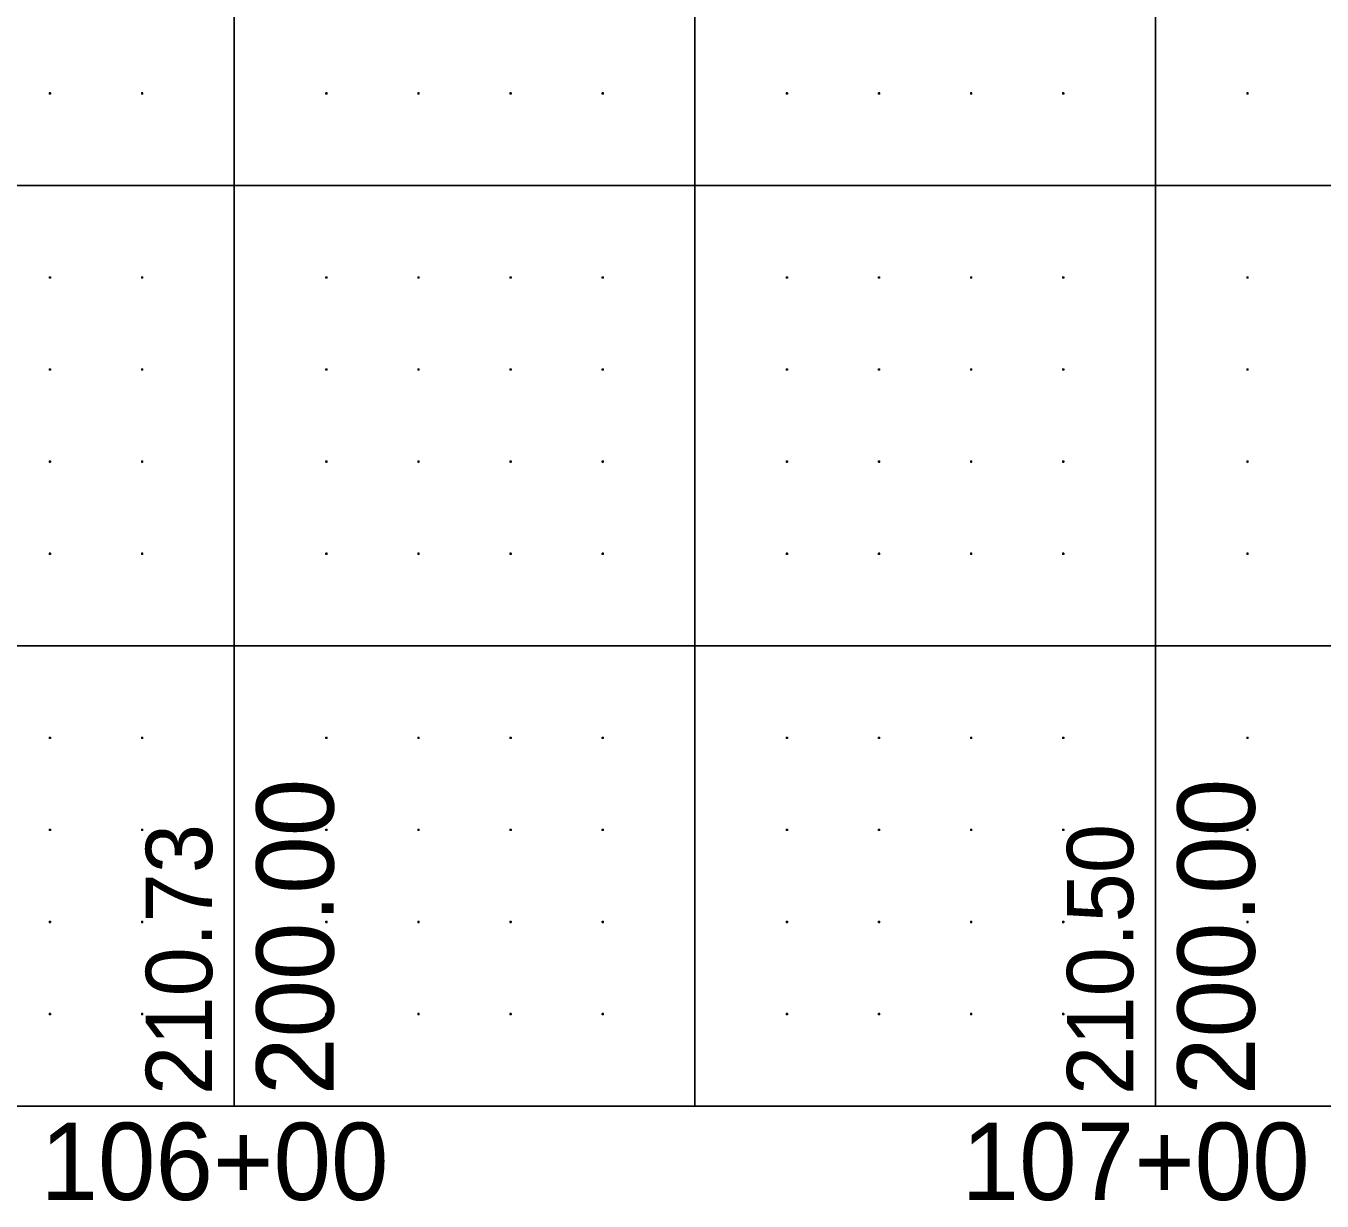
# Model space of a CAD drawing. Extents: x 471 to 2121, y 140 to 650.
# Drawn here: x 1213.4 to 1354.2, y 139.7 to 267.3 of the extents above; entities that cross this region are included whole.
import ezdxf

# ---------------------------------------------------------------- set-up
doc = ezdxf.new("R2010")
doc.units = 0
for name, color, linetype in [('DSN_DRFT_Border Grid', 7, 'Continuous'), ('DSN_RDWY_Prof Annotation', 7, 'Continuous'), ('EX_Profile Annotation', 7, 'Continuous')]:
    doc.layers.add(name, color=color, linetype=linetype)

msp = doc.modelspace()

# ---------------------------------------------------------------- linework, layer by layer
at = {"layer": 'DSN_DRFT_Border Grid'}
for p, q in [((1236.06, 150), (1236.06, 650)), ((1236.06, 150), (1236.06, 650)), ((1286.06, 150), (1286.06, 650)), ((1286.06, 150), (1286.06, 650)), ((1336.06, 150), (1336.06, 650)), ((1336.06, 150), (1336.06, 650)), ((1216.18, 260), (1215.94, 260)), ((1216.18, 260), (1215.94, 260)), ((1216.06, 260.12), (1216.06, 259.88)), ((1216.06, 260.12), (1216.06, 259.88)), ((1226.18, 260), (1225.94, 260)), ((1226.18, 260), (1225.94, 260)), ((1226.06, 260.12), (1226.06, 259.88)), ((1226.06, 260.12), (1226.06, 259.88)), ((1246.18, 260), (1245.94, 260)), ((1246.18, 260), (1245.94, 260)), ((1246.06, 260.12), (1246.06, 259.88)), ((1246.06, 260.12), (1246.06, 259.88)), ((1256.18, 260), (1255.94, 260)), ((1256.18, 260), (1255.94, 260)), ((1256.06, 260.12), (1256.06, 259.88)), ((1256.06, 260.12), (1256.06, 259.88)), ((1266.18, 260), (1265.94, 260)), ((1266.18, 260), (1265.94, 260)), ((1266.06, 260.12), (1266.06, 259.88)), ((1266.06, 260.12), (1266.06, 259.88)), ((1276.18, 260), (1275.94, 260)), ((1276.18, 260), (1275.94, 260)), ((1276.06, 260.12), (1276.06, 259.88)), ((1276.06, 260.12), (1276.06, 259.88)), ((1296.18, 260), (1295.94, 260)), ((1296.18, 260), (1295.94, 260)), ((1296.06, 260.12), (1296.06, 259.88)), ((1296.06, 260.12), (1296.06, 259.88)), ((1306.18, 260), (1305.94, 260)), ((1306.18, 260), (1305.94, 260)), ((1306.06, 260.12), (1306.06, 259.88)), ((1306.06, 260.12), (1306.06, 259.88)), ((1316.18, 260), (1315.94, 260)), ((1316.18, 260), (1315.94, 260)), ((1316.06, 260.12), (1316.06, 259.88)), ((1316.06, 260.12), (1316.06, 259.88)), ((1326.18, 260), (1325.94, 260)), ((1326.18, 260), (1325.94, 260)), ((1326.06, 260.12), (1326.06, 259.88)), ((1326.06, 260.12), (1326.06, 259.88)), ((1346.18, 260), (1345.94, 260)), ((1346.18, 260), (1345.94, 260)), ((1346.06, 260.12), (1346.06, 259.88)), ((1346.06, 260.12), (1346.06, 259.88)), ((521.06, 250), (2071.06, 250)), ((521.06, 250), (2071.06, 250)), ((1216.18, 240), (1215.94, 240)), ((1216.18, 240), (1215.94, 240)), ((1216.06, 240.12), (1216.06, 239.88)), ((1216.06, 240.12), (1216.06, 239.88)), ((1226.18, 240), (1225.94, 240)), ((1226.18, 240), (1225.94, 240)), ((1226.06, 240.12), (1226.06, 239.88)), ((1226.06, 240.12), (1226.06, 239.88)), ((1246.18, 240), (1245.94, 240)), ((1246.18, 240), (1245.94, 240)), ((1246.06, 240.12), (1246.06, 239.88)), ((1246.06, 240.12), (1246.06, 239.88)), ((1256.18, 240), (1255.94, 240)), ((1256.18, 240), (1255.94, 240)), ((1256.06, 240.12), (1256.06, 239.88)), ((1256.06, 240.12), (1256.06, 239.88)), ((1266.18, 240), (1265.94, 240)), ((1266.18, 240), (1265.94, 240)), ((1266.06, 240.12), (1266.06, 239.88)), ((1266.06, 240.12), (1266.06, 239.88)), ((1276.18, 240), (1275.94, 240)), ((1276.18, 240), (1275.94, 240)), ((1276.06, 240.12), (1276.06, 239.88)), ((1276.06, 240.12), (1276.06, 239.88)), ((1296.18, 240), (1295.94, 240)), ((1296.18, 240), (1295.94, 240)), ((1296.06, 240.12), (1296.06, 239.88)), ((1296.06, 240.12), (1296.06, 239.88)), ((1306.18, 240), (1305.94, 240)), ((1306.18, 240), (1305.94, 240)), ((1306.06, 240.12), (1306.06, 239.88)), ((1306.06, 240.12), (1306.06, 239.88)), ((1316.18, 240), (1315.94, 240)), ((1316.18, 240), (1315.94, 240)), ((1316.06, 240.12), (1316.06, 239.88)), ((1316.06, 240.12), (1316.06, 239.88)), ((1326.18, 240), (1325.94, 240)), ((1326.18, 240), (1325.94, 240)), ((1326.06, 240.12), (1326.06, 239.88)), ((1326.06, 240.12), (1326.06, 239.88)), ((1346.18, 240), (1345.94, 240)), ((1346.18, 240), (1345.94, 240)), ((1346.06, 240.12), (1346.06, 239.88)), ((1346.06, 240.12), (1346.06, 239.88)), ((1216.18, 230), (1215.94, 230)), ((1216.18, 230), (1215.94, 230)), ((1216.06, 230.12), (1216.06, 229.88)), ((1216.06, 230.12), (1216.06, 229.88)), ((1226.18, 230), (1225.94, 230)), ((1226.18, 230), (1225.94, 230)), ((1226.06, 230.12), (1226.06, 229.88)), ((1226.06, 230.12), (1226.06, 229.88)), ((1246.18, 230), (1245.94, 230)), ((1246.18, 230), (1245.94, 230)), ((1246.06, 230.12), (1246.06, 229.88)), ((1246.06, 230.12), (1246.06, 229.88)), ((1256.18, 230), (1255.94, 230)), ((1256.18, 230), (1255.94, 230)), ((1256.06, 230.12), (1256.06, 229.88)), ((1256.06, 230.12), (1256.06, 229.88)), ((1266.18, 230), (1265.94, 230)), ((1266.18, 230), (1265.94, 230)), ((1266.06, 230.12), (1266.06, 229.88)), ((1266.06, 230.12), (1266.06, 229.88)), ((1276.18, 230), (1275.94, 230)), ((1276.18, 230), (1275.94, 230)), ((1276.06, 230.12), (1276.06, 229.88)), ((1276.06, 230.12), (1276.06, 229.88)), ((1296.18, 230), (1295.94, 230)), ((1296.18, 230), (1295.94, 230)), ((1296.06, 230.12), (1296.06, 229.88)), ((1296.06, 230.12), (1296.06, 229.88)), ((1306.18, 230), (1305.94, 230)), ((1306.18, 230), (1305.94, 230)), ((1306.06, 230.12), (1306.06, 229.88)), ((1306.06, 230.12), (1306.06, 229.88)), ((1316.18, 230), (1315.94, 230)), ((1316.18, 230), (1315.94, 230)), ((1316.06, 230.12), (1316.06, 229.88)), ((1316.06, 230.12), (1316.06, 229.88)), ((1326.18, 230), (1325.94, 230)), ((1326.18, 230), (1325.94, 230)), ((1326.06, 230.12), (1326.06, 229.88)), ((1326.06, 230.12), (1326.06, 229.88)), ((1346.18, 230), (1345.94, 230)), ((1346.18, 230), (1345.94, 230)), ((1346.06, 230.12), (1346.06, 229.88)), ((1346.06, 230.12), (1346.06, 229.88)), ((1216.18, 220), (1215.94, 220)), ((1216.18, 220), (1215.94, 220)), ((1216.06, 220.12), (1216.06, 219.88)), ((1216.06, 220.12), (1216.06, 219.88)), ((1226.18, 220), (1225.94, 220)), ((1226.18, 220), (1225.94, 220)), ((1226.06, 220.12), (1226.06, 219.88)), ((1226.06, 220.12), (1226.06, 219.88)), ((1246.18, 220), (1245.94, 220)), ((1246.18, 220), (1245.94, 220)), ((1246.06, 220.12), (1246.06, 219.88)), ((1246.06, 220.12), (1246.06, 219.88)), ((1256.18, 220), (1255.94, 220)), ((1256.18, 220), (1255.94, 220)), ((1256.06, 220.12), (1256.06, 219.88)), ((1256.06, 220.12), (1256.06, 219.88)), ((1266.18, 220), (1265.94, 220)), ((1266.18, 220), (1265.94, 220)), ((1266.06, 220.12), (1266.06, 219.88)), ((1266.06, 220.12), (1266.06, 219.88)), ((1276.18, 220), (1275.94, 220)), ((1276.18, 220), (1275.94, 220)), ((1276.06, 220.12), (1276.06, 219.88)), ((1276.06, 220.12), (1276.06, 219.88)), ((1296.18, 220), (1295.94, 220)), ((1296.18, 220), (1295.94, 220)), ((1296.06, 220.12), (1296.06, 219.88)), ((1296.06, 220.12), (1296.06, 219.88)), ((1306.18, 220), (1305.94, 220)), ((1306.18, 220), (1305.94, 220)), ((1306.06, 220.12), (1306.06, 219.88)), ((1306.06, 220.12), (1306.06, 219.88)), ((1316.18, 220), (1315.94, 220)), ((1316.18, 220), (1315.94, 220)), ((1316.06, 220.12), (1316.06, 219.88)), ((1316.06, 220.12), (1316.06, 219.88)), ((1326.18, 220), (1325.94, 220)), ((1326.18, 220), (1325.94, 220)), ((1326.06, 220.12), (1326.06, 219.88)), ((1326.06, 220.12), (1326.06, 219.88)), ((1346.18, 220), (1345.94, 220)), ((1346.18, 220), (1345.94, 220)), ((1346.06, 220.12), (1346.06, 219.88)), ((1346.06, 220.12), (1346.06, 219.88)), ((1216.18, 210), (1215.94, 210)), ((1216.18, 210), (1215.94, 210)), ((1216.06, 210.12), (1216.06, 209.88)), ((1216.06, 210.12), (1216.06, 209.88)), ((1226.18, 210), (1225.94, 210)), ((1226.18, 210), (1225.94, 210)), ((1226.06, 210.12), (1226.06, 209.88)), ((1226.06, 210.12), (1226.06, 209.88)), ((1246.18, 210), (1245.94, 210)), ((1246.18, 210), (1245.94, 210)), ((1246.06, 210.12), (1246.06, 209.88)), ((1246.06, 210.12), (1246.06, 209.88)), ((1256.18, 210), (1255.94, 210)), ((1256.18, 210), (1255.94, 210)), ((1256.06, 210.12), (1256.06, 209.88)), ((1256.06, 210.12), (1256.06, 209.88)), ((1266.18, 210), (1265.94, 210)), ((1266.18, 210), (1265.94, 210)), ((1266.06, 210.12), (1266.06, 209.88)), ((1266.06, 210.12), (1266.06, 209.88)), ((1276.18, 210), (1275.94, 210)), ((1276.18, 210), (1275.94, 210)), ((1276.06, 210.12), (1276.06, 209.88)), ((1276.06, 210.12), (1276.06, 209.88)), ((1296.18, 210), (1295.94, 210)), ((1296.18, 210), (1295.94, 210)), ((1296.06, 210.12), (1296.06, 209.88)), ((1296.06, 210.12), (1296.06, 209.88)), ((1306.18, 210), (1305.94, 210)), ((1306.18, 210), (1305.94, 210)), ((1306.06, 210.12), (1306.06, 209.88)), ((1306.06, 210.12), (1306.06, 209.88)), ((1316.18, 210), (1315.94, 210)), ((1316.18, 210), (1315.94, 210)), ((1316.06, 210.12), (1316.06, 209.88)), ((1316.06, 210.12), (1316.06, 209.88)), ((1326.18, 210), (1325.94, 210)), ((1326.18, 210), (1325.94, 210)), ((1326.06, 210.12), (1326.06, 209.88)), ((1326.06, 210.12), (1326.06, 209.88)), ((1346.18, 210), (1345.94, 210)), ((1346.18, 210), (1345.94, 210)), ((1346.06, 210.12), (1346.06, 209.88)), ((1346.06, 210.12), (1346.06, 209.88)), ((521.06, 200), (2071.06, 200)), ((521.06, 200), (2071.06, 200)), ((1216.18, 190), (1215.94, 190)), ((1216.18, 190), (1215.94, 190)), ((1216.06, 190.12), (1216.06, 189.88)), ((1216.06, 190.12), (1216.06, 189.88)), ((1226.18, 190), (1225.94, 190)), ((1226.18, 190), (1225.94, 190)), ((1226.06, 190.12), (1226.06, 189.88)), ((1226.06, 190.12), (1226.06, 189.88)), ((1246.18, 190), (1245.94, 190)), ((1246.18, 190), (1245.94, 190)), ((1246.06, 190.12), (1246.06, 189.88)), ((1246.06, 190.12), (1246.06, 189.88)), ((1256.18, 190), (1255.94, 190)), ((1256.18, 190), (1255.94, 190)), ((1256.06, 190.12), (1256.06, 189.88)), ((1256.06, 190.12), (1256.06, 189.88)), ((1266.18, 190), (1265.94, 190)), ((1266.18, 190), (1265.94, 190)), ((1266.06, 190.12), (1266.06, 189.88)), ((1266.06, 190.12), (1266.06, 189.88)), ((1276.18, 190), (1275.94, 190)), ((1276.18, 190), (1275.94, 190)), ((1276.06, 190.12), (1276.06, 189.88)), ((1276.06, 190.12), (1276.06, 189.88)), ((1296.18, 190), (1295.94, 190)), ((1296.18, 190), (1295.94, 190)), ((1296.06, 190.12), (1296.06, 189.88)), ((1296.06, 190.12), (1296.06, 189.88)), ((1306.18, 190), (1305.94, 190)), ((1306.18, 190), (1305.94, 190)), ((1306.06, 190.12), (1306.06, 189.88)), ((1306.06, 190.12), (1306.06, 189.88)), ((1316.18, 190), (1315.94, 190)), ((1316.18, 190), (1315.94, 190)), ((1316.06, 190.12), (1316.06, 189.88)), ((1316.06, 190.12), (1316.06, 189.88)), ((1326.18, 190), (1325.94, 190)), ((1326.18, 190), (1325.94, 190)), ((1326.06, 190.12), (1326.06, 189.88)), ((1326.06, 190.12), (1326.06, 189.88)), ((1346.18, 190), (1345.94, 190)), ((1346.18, 190), (1345.94, 190)), ((1346.06, 190.12), (1346.06, 189.88)), ((1346.06, 190.12), (1346.06, 189.88)), ((1216.06, 180.12), (1216.06, 179.88)), ((1216.06, 180.12), (1216.06, 179.88)), ((1226.06, 180.12), (1226.06, 179.88)), ((1226.06, 180.12), (1226.06, 179.88)), ((1246.06, 180.12), (1246.06, 179.88)), ((1246.06, 180.12), (1246.06, 179.88)), ((1256.06, 180.12), (1256.06, 179.88)), ((1256.06, 180.12), (1256.06, 179.88)), ((1266.06, 180.12), (1266.06, 179.88)), ((1266.06, 180.12), (1266.06, 179.88)), ((1276.06, 180.12), (1276.06, 179.88)), ((1276.06, 180.12), (1276.06, 179.88)), ((1296.06, 180.12), (1296.06, 179.88)), ((1296.06, 180.12), (1296.06, 179.88)), ((1306.06, 180.12), (1306.06, 179.88)), ((1306.06, 180.12), (1306.06, 179.88)), ((1316.06, 180.12), (1316.06, 179.88)), ((1316.06, 180.12), (1316.06, 179.88)), ((1326.06, 180.12), (1326.06, 179.88)), ((1326.06, 180.12), (1326.06, 179.88)), ((1346.06, 180.12), (1346.06, 179.88)), ((1346.06, 180.12), (1346.06, 179.88)), ((1216.18, 180), (1215.94, 180)), ((1216.18, 180), (1215.94, 180)), ((1226.18, 180), (1225.94, 180)), ((1226.18, 180), (1225.94, 180)), ((1246.18, 180), (1245.94, 180)), ((1246.18, 180), (1245.94, 180)), ((1256.18, 180), (1255.94, 180)), ((1256.18, 180), (1255.94, 180)), ((1266.18, 180), (1265.94, 180)), ((1266.18, 180), (1265.94, 180)), ((1276.18, 180), (1275.94, 180)), ((1276.18, 180), (1275.94, 180)), ((1296.18, 180), (1295.94, 180)), ((1296.18, 180), (1295.94, 180)), ((1306.18, 180), (1305.94, 180)), ((1306.18, 180), (1305.94, 180)), ((1316.18, 180), (1315.94, 180)), ((1316.18, 180), (1315.94, 180)), ((1326.18, 180), (1325.94, 180)), ((1326.18, 180), (1325.94, 180)), ((1346.18, 180), (1345.94, 180)), ((1346.18, 180), (1345.94, 180)), ((1216.18, 170), (1215.94, 170)), ((1216.18, 170), (1215.94, 170)), ((1216.06, 170.12), (1216.06, 169.88)), ((1216.06, 170.12), (1216.06, 169.88)), ((1226.18, 170), (1225.94, 170)), ((1226.18, 170), (1225.94, 170)), ((1226.06, 170.12), (1226.06, 169.88)), ((1226.06, 170.12), (1226.06, 169.88)), ((1246.18, 170), (1245.94, 170)), ((1246.18, 170), (1245.94, 170)), ((1246.06, 170.12), (1246.06, 169.88)), ((1246.06, 170.12), (1246.06, 169.88)), ((1256.18, 170), (1255.94, 170)), ((1256.18, 170), (1255.94, 170)), ((1256.06, 170.12), (1256.06, 169.88)), ((1256.06, 170.12), (1256.06, 169.88)), ((1266.18, 170), (1265.94, 170)), ((1266.18, 170), (1265.94, 170)), ((1266.06, 170.12), (1266.06, 169.88)), ((1266.06, 170.12), (1266.06, 169.88)), ((1276.18, 170), (1275.94, 170)), ((1276.18, 170), (1275.94, 170)), ((1276.06, 170.12), (1276.06, 169.88)), ((1276.06, 170.12), (1276.06, 169.88)), ((1296.18, 170), (1295.94, 170)), ((1296.18, 170), (1295.94, 170)), ((1296.06, 170.12), (1296.06, 169.88)), ((1296.06, 170.12), (1296.06, 169.88)), ((1306.18, 170), (1305.94, 170)), ((1306.18, 170), (1305.94, 170)), ((1306.06, 170.12), (1306.06, 169.88)), ((1306.06, 170.12), (1306.06, 169.88)), ((1316.18, 170), (1315.94, 170)), ((1316.18, 170), (1315.94, 170)), ((1316.06, 170.12), (1316.06, 169.88)), ((1316.06, 170.12), (1316.06, 169.88)), ((1326.18, 170), (1325.94, 170)), ((1326.18, 170), (1325.94, 170)), ((1326.06, 170.12), (1326.06, 169.88)), ((1326.06, 170.12), (1326.06, 169.88)), ((1346.18, 170), (1345.94, 170)), ((1346.18, 170), (1345.94, 170)), ((1346.06, 170.12), (1346.06, 169.88)), ((1346.06, 170.12), (1346.06, 169.88)), ((1216.18, 160), (1215.94, 160)), ((1216.18, 160), (1215.94, 160)), ((1216.06, 160.12), (1216.06, 159.88)), ((1216.06, 160.12), (1216.06, 159.88)), ((1226.18, 160), (1225.94, 160)), ((1226.18, 160), (1225.94, 160)), ((1226.06, 160.12), (1226.06, 159.88)), ((1226.06, 160.12), (1226.06, 159.88)), ((1246.18, 160), (1245.94, 160)), ((1246.18, 160), (1245.94, 160)), ((1246.06, 160.12), (1246.06, 159.88)), ((1246.06, 160.12), (1246.06, 159.88)), ((1256.18, 160), (1255.94, 160)), ((1256.18, 160), (1255.94, 160)), ((1256.06, 160.12), (1256.06, 159.88)), ((1256.06, 160.12), (1256.06, 159.88)), ((1266.18, 160), (1265.94, 160)), ((1266.18, 160), (1265.94, 160)), ((1266.06, 160.12), (1266.06, 159.88)), ((1266.06, 160.12), (1266.06, 159.88)), ((1276.18, 160), (1275.94, 160)), ((1276.18, 160), (1275.94, 160)), ((1276.06, 160.12), (1276.06, 159.88)), ((1276.06, 160.12), (1276.06, 159.88)), ((1296.18, 160), (1295.94, 160)), ((1296.18, 160), (1295.94, 160)), ((1296.06, 160.12), (1296.06, 159.88)), ((1296.06, 160.12), (1296.06, 159.88)), ((1306.18, 160), (1305.94, 160)), ((1306.18, 160), (1305.94, 160)), ((1306.06, 160.12), (1306.06, 159.88)), ((1306.06, 160.12), (1306.06, 159.88)), ((1316.18, 160), (1315.94, 160)), ((1316.18, 160), (1315.94, 160)), ((1316.06, 160.12), (1316.06, 159.88)), ((1316.06, 160.12), (1316.06, 159.88)), ((1326.18, 160), (1325.94, 160)), ((1326.18, 160), (1325.94, 160)), ((1326.06, 160.12), (1326.06, 159.88)), ((1326.06, 160.12), (1326.06, 159.88)), ((1346.18, 160), (1345.94, 160)), ((1346.18, 160), (1345.94, 160)), ((1346.06, 160.12), (1346.06, 159.88)), ((1346.06, 160.12), (1346.06, 159.88)), ((521.06, 150), (2071.06, 150)), ((521.06, 150), (2071.06, 150))]:
    msp.add_line(p, q, dxfattribs=at)

# ---------------------------------------------------------------- texts
at = {"layer": 'DSN_RDWY_Prof Annotation'}
for p in [(1246.86, 151.2), (1346.86, 151.2)]:
    msp.add_text('200.00', height=8.4, rotation=90, dxfattribs=at).set_placement(p)
for s, p in [('106+00', (1215.02, 139.8)), ('106+00', (1215.02, 139.8)), ('107+00', (1315.02, 139.8)), ('107+00', (1315.02, 139.8))]:
    msp.add_text(s, height=8.4, dxfattribs=at).set_placement(p)
at = {"layer": 'EX_Profile Annotation'}
for s, p in [('210.73', (1233.66, 151.2)), ('210.50', (1333.66, 151.2))]:
    msp.add_text(s, height=7.2, rotation=90, dxfattribs=at).set_placement(p)

doc.saveas('drawing.dxf')
